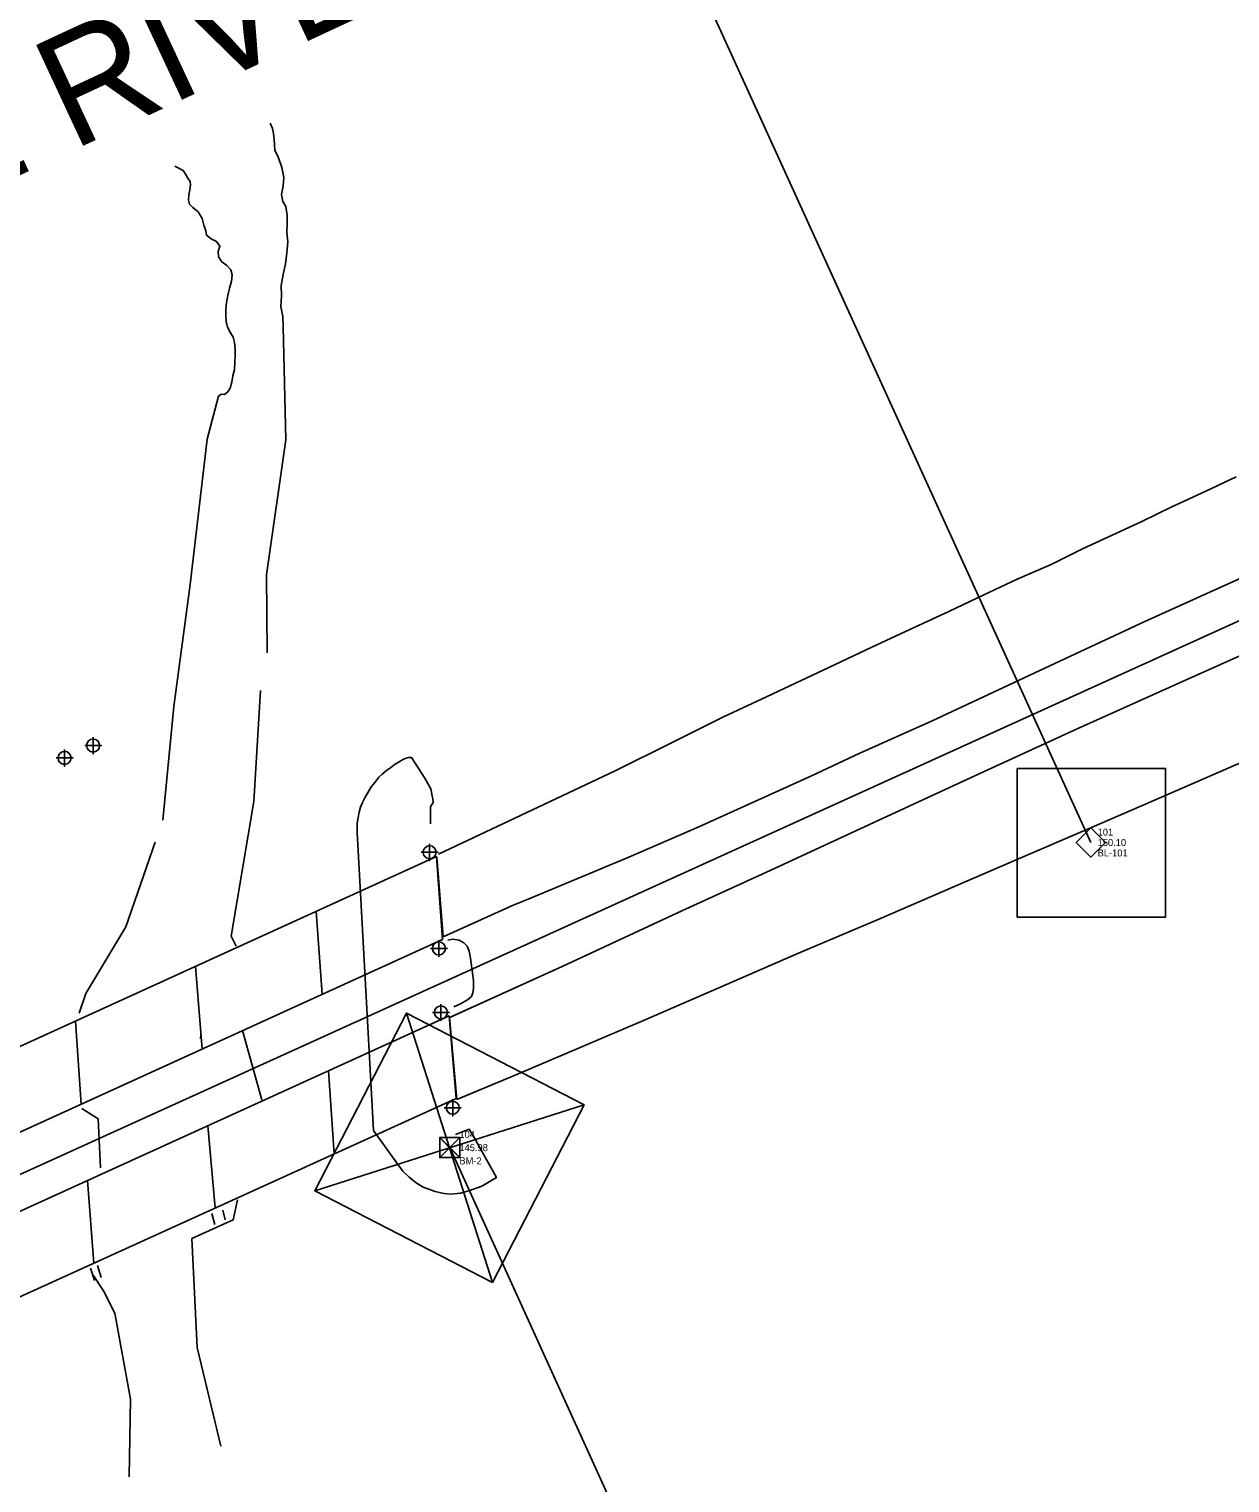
# Model space of a CAD drawing. Extents: x 2243531 to 2252747, y 658714 to 667210.
# Drawn here: x 2248974 to 2249406, y 663262 to 663785 of the extents above; entities that cross this region are included whole.
import ezdxf

# ---------------------------------------------------------------- set-up
doc = ezdxf.new("R2010")
doc.units = 0
for name, color, linetype in [('CTL Bench Mark CELL', 7, 'Continuous'), ('CTL Bench Mark Cogo Comment', 7, 'Continuous'), ('CTL Bench Mark Cogo Elevation', 7, 'Continuous'), ('CTL Bench Mark Cogo Number', 7, 'Continuous'), ('CTL NGS Horizontal CELL', 7, 'Continuous'), ('CTL Supplemental Horizontal and Vertical CELL', 7, 'Continuous'), ('CTL Supplemental Horizontal and Vertical Cogo Comment', 7, 'Continuous'), ('CTL Supplemental Horizontal and Vertical Cogo Elevation', 7, 'Continuous'), ('CTL Supplemental Horizontal and Vertical Cogo Number', 7, 'Continuous'), ('Exist Building', 7, 'Continuous'), ('Exist DTM Regular Point CELL', 7, 'Continuous'), ('Exist Hydro Stream or Body of Water', 7, 'Continuous'), ('Exist Hydro Stream or Body of Water Text', 7, 'Continuous'), ('Exist Other Culture Area Outline', 7, 'Continuous'), ('Exist Roads EOP', 7, 'Continuous'), ('Exist Structure Major Bridge Seam', 7, 'Continuous'), ('Exist Structure Major Deck Tunnel Box Culvert', 7, 'Continuous'), ('Exist Utilities Sanitary Sewer AG Line Cogo Point CELL', 7, 'Continuous'), ('Prop Horizontal Alignment', 7, 'Continuous')]:
    doc.layers.add(name, color=color, linetype=linetype)

# ---------------------------------------------------------------- blocks, each defined once
blk = doc.blocks.new('CTL BENCH MARK')
at = {"layer": 'CTL Bench Mark CELL'}
blk.add_line((0, 0), (0, 0), dxfattribs=at)
blk.add_lwpolyline([(-0.072, 0.07175), (0.07175, 0.07175), (0.07175, -0.072), (-0.072, -0.072)], close=True, dxfattribs=at)
for points in [[(0.07175, 0.07175), (-0.072, -0.072), (-0.000125, -0.000125), (0.07175, -0.072), (-0.072, 0.07175)], [(-0.000125, -0.000125), (0.07175, 0.07175), (-0.072, 0.07175), (-0.000125, -0.000125)], [(-0.000125, -0.000125), (-0.072, -0.072), (0.07175, -0.072), (-0.000125, -0.000125)]]:
    blk.add_lwpolyline(points, dxfattribs=at)

msp = doc.modelspace()

# ---------------------------------------------------------------- linework, layer by layer
at = {"layer": 'CTL Bench Mark CELL'}
msp.add_line((2249125.57, 663382.51), (2249125.57, 663382.51), dxfattribs=at)
msp.add_line((2249125.57, 663382.51), (2249125.57, 663382.51), dxfattribs=at)
for points in [[(2249110.03, 663430.9), (2249173.9, 663397.94), (2249140.94, 663334.07), (2249077.07, 663367.03)], [(2249121.97, 663386.1), (2249129.16, 663386.1), (2249129.16, 663378.91), (2249121.97, 663378.91)]]:
    msp.add_lwpolyline(points, close=True, dxfattribs=at)
for points in [[(2249173.9, 663397.94), (2249077.07, 663367.03), (2249125.48, 663382.48), (2249140.94, 663334.07), (2249110.03, 663430.9)], [(2249125.48, 663382.48), (2249173.9, 663397.94), (2249110.03, 663430.9), (2249125.48, 663382.48)], [(2249125.48, 663382.48), (2249077.07, 663367.03), (2249140.94, 663334.07), (2249125.48, 663382.48)], [(2249129.16, 663386.1), (2249121.97, 663378.91), (2249125.56, 663382.5), (2249129.16, 663378.91), (2249121.97, 663386.1)], [(2249125.56, 663382.5), (2249129.16, 663386.1), (2249121.97, 663386.1), (2249125.56, 663382.5)], [(2249125.56, 663382.5), (2249121.97, 663378.91), (2249129.16, 663378.91), (2249125.56, 663382.5)]]:
    msp.add_lwpolyline(points, dxfattribs=at)
at = {"layer": 'CTL NGS Horizontal CELL'}
for p, q in [((2249355.99, 663492.2), (2249171.33, 663897.43)), ((2249125.57, 663382.51), (2249398.31, 662783.98))]:
    msp.add_line(p, q, dxfattribs=at)
at = {"layer": 'CTL Supplemental Horizontal and Vertical CELL'}
msp.add_line((2249355.99, 663492.2), (2249355.99, 663492.2), dxfattribs=at)
msp.add_line((2249355.99, 663492.2), (2249355.99, 663492.2), dxfattribs=at)
for points in [[(2249329.53, 663518.84), (2249382.9, 663518.84), (2249382.9, 663465.38), (2249329.53, 663465.38)], [(2249350.78, 663492.22), (2249356.02, 663497.46), (2249361.27, 663492.21), (2249356.03, 663486.97)]]:
    msp.add_lwpolyline(points, close=True, dxfattribs=at)
at = {"layer": 'Exist Building'}
msp.add_lwpolyline([(2249124.85, 663457.1), (2249126.66, 663457.44), (2249129.03, 663457.08), (2249130.68, 663456.17), (2249131.84, 663454.99), (2249132.58, 663453.19), (2249133.08, 663450.58), (2249134.12, 663442.59), (2249134.16, 663439.75), (2249133.89, 663438.18), (2249133.42, 663436.82), (2249132, 663435.63), (2249129.47, 663434.25), (2249127.04, 663433.17)], dxfattribs=at)
at = {"layer": 'Exist DTM Regular Point CELL'}
for points in [[(2249118.36, 663491.68), (2249118.36, 663485.68), (2249118.36, 663488.68), (2249121.36, 663488.68), (2249115.36, 663488.68)], [(2249121.67, 663457.14), (2249121.67, 663451.14), (2249121.67, 663454.14), (2249124.67, 663454.14), (2249118.67, 663454.14)], [(2249122.42, 663434.14), (2249122.42, 663428.14), (2249122.42, 663431.14), (2249125.42, 663431.14), (2249119.42, 663431.14)], [(2249126.64, 663399.88), (2249126.64, 663393.88), (2249126.64, 663396.88), (2249129.64, 663396.88), (2249123.64, 663396.88)]]:
    msp.add_lwpolyline(points, dxfattribs=at)
for centre in [(2249118.36, 663488.68), (2249121.67, 663454.14), (2249122.42, 663431.14), (2249126.64, 663396.88)]:
    msp.add_circle(centre, 2.34, dxfattribs=at)
at = {"layer": 'Exist Hydro Stream or Body of Water'}
for p, q in [((2249065.73, 663677.55), (2249066.64, 663636.91)), ((2249038.37, 663637.24), (2249042.46, 663652.6))]:
    msp.add_line(p, q, dxfattribs=at)
for points in [[(2249061.02, 663750.86), (2249061.84, 663748.84), (2249062.29, 663747.05), (2249062.49, 663744.92)], [(2249065.73, 663677.55), (2249065.64, 663681.31), (2249064.93, 663684.9), (2249065.16, 663688.71), (2249065.03, 663692.42), (2249065.69, 663696.4), (2249066.49, 663700.18), (2249067.06, 663704.14), (2249067.42, 663708.16), (2249067.05, 663711.65), (2249067.11, 663714.73), (2249067.14, 663717.74), (2249066.64, 663720.83), (2249065.57, 663722.6), (2249065.11, 663725.16), (2249065.75, 663728.26), (2249065.96, 663731.21), (2249065.2, 663734.92), (2249064.03, 663738.34), (2249062.68, 663741.06), (2249062.49, 663744.92)], [(2249026.78, 663735.33), (2249029.78, 663733.77), (2249030.82, 663732.14), (2249031.5, 663731.04)], [(2249031.5, 663731.04), (2249031.5, 663731.04), (2249032.23, 663729.85), (2249032.43, 663728.66), (2249032.1, 663726.82), (2249031.76, 663725.01), (2249031.66, 663723.11), (2249032.09, 663721.71), (2249033.22, 663720.54), (2249035.12, 663718.9), (2249036.57, 663716.57), (2249037.21, 663714.17), (2249037.97, 663712.08), (2249038.2, 663710.51), (2249039.88, 663709.19), (2249041.74, 663708.27), (2249042.96, 663706.58), (2249042.36, 663704.61), (2249042.46, 663702.77), (2249043.62, 663700.93), (2249045.4, 663699.68), (2249046.86, 663698.13), (2249047.39, 663696.28), (2249047.18, 663694), (2249046.42, 663691.54), (2249045.82, 663688.89), (2249045.31, 663686.31), (2249045.14, 663684.1), (2249045.15, 663681.76), (2249045.23, 663679.49), (2249045.67, 663677.46), (2249046.75, 663675.48), (2249047.75, 663673.86), (2249048.24, 663671.99), (2249048.43, 663669.68), (2249048.49, 663667.26), (2249048.37, 663664.91), (2249048.2, 663662.22), (2249047.66, 663660.01), (2249047.2, 663657.75), (2249046.7, 663655.52), (2249045.67, 663654.09), (2249044.59, 663653.29), (2249043.41, 663653.4), (2249042.46, 663652.6)], [(2249022.44, 663500.21), (2249026.42, 663541.08), (2249032.24, 663584.97), (2249038.37, 663637.24)], [(2249066.64, 663636.91), (2249059.66, 663588.47), (2249059.92, 663560.38)], [(2249048.87, 663454.89), (2249047.04, 663458.48), (2249055.21, 663506.91), (2249057.52, 663546.8)], [(2248992.36, 663430.87), (2248994.77, 663437.93), (2249009.16, 663461.86), (2249019.73, 663492.37)], [(2249058.09, 663399.69), (2249051.04, 663424.61)], [(2249000.08, 663375.26), (2248999.2, 663392.91), (2248993.35, 663396.62)], [(2249043.28, 663275.16), (2249034.74, 663310.69), (2249032.88, 663349.79), (2249047.74, 663356.61), (2249049.28, 663363.69)], [(2249010.31, 663264.12), (2249010.83, 663292.06), (2249005.15, 663322.96), (2249001.16, 663330.99), (2248997.43, 663336.68)]]:
    msp.add_lwpolyline(points, dxfattribs=at)
at = {"layer": 'Exist Other Culture Area Outline'}
msp.add_line((2249106.69, 663376.77), (2249098.21, 663388.67), dxfattribs=at)
for points in [[(2249098.21, 663388.67), (2249092.27, 663495.75), (2249092.34, 663499.12), (2249092.65, 663501.16), (2249092.99, 663503.09), (2249093.5, 663504.95), (2249094.23, 663506.57), (2249095.1, 663508.23), (2249096.4, 663510.56), (2249097.39, 663512.19), (2249098.2, 663513.21), (2249099.14, 663514.43), (2249100.13, 663515.68), (2249101.26, 663516.79), (2249102.88, 663518.09), (2249104.39, 663519.21), (2249105.94, 663520.32), (2249107.43, 663521.23), (2249108.96, 663522.13), (2249110.67, 663522.75), (2249111.88, 663522.74), (2249116.58, 663515.39), (2249118.82, 663511.54), (2249119.5, 663507.77), (2249119.58, 663506.58), (2249118.68, 663505.01), (2249118.65, 663498.96)], [(2249134.33, 663386.18), (2249132.58, 663389.1), (2249127.68, 663387.18)], [(2249134.33, 663386.18), (2249142.35, 663371.73), (2249137.15, 663368.68), (2249132.42, 663366.98), (2249129.41, 663366.12), (2249125.94, 663365.8), (2249123.51, 663365.97), (2249120.33, 663366.74), (2249115.99, 663368.34), (2249113.54, 663369.81), (2249111, 663371.88), (2249108.76, 663374.1), (2249106.69, 663376.77), (2249105.76, 663378.29)], [(2249040.12, 663358.88), (2249041.11, 663354.93)], [(2249044.07, 663360.03), (2249044.89, 663356.58)], [(2248996.48, 663339.15), (2248997.89, 663334.73)], [(2248999.01, 663340.09), (2249000.33, 663335.86)]]:
    msp.add_lwpolyline(points, dxfattribs=at)
at = {"layer": 'Exist Roads EOP'}
msp.add_line((2249185.02, 663517.98), (2249121.56, 663487.99), dxfattribs=at)
for points in [[(2249748.92, 663712.77), (2249733.4, 663705.13), (2249725.89, 663702.15), (2249693.85, 663687.77), (2249660.73, 663672.87), (2249633.88, 663661.38), (2249603.61, 663647.21), (2249563.33, 663629.32), (2249529.77, 663614.02), (2249493.93, 663597.97), (2249458.47, 663581.35), (2249425.6, 663566.47), (2249386.57, 663548.98), (2249351.1, 663533.06), (2249316.09, 663516.96), (2249277.98, 663499.39), (2249240.81, 663482.13), (2249208.98, 663467.59), (2249166.03, 663447.67), (2249125.56, 663429.26)], [(2249748.92, 663712.77), (2249733.4, 663705.13), (2249725.89, 663702.15), (2249693.85, 663687.77), (2249660.73, 663672.87), (2249633.88, 663661.38), (2249603.61, 663647.21), (2249563.33, 663629.32), (2249529.77, 663614.02), (2249493.93, 663597.97), (2249458.47, 663581.35), (2249425.6, 663566.47), (2249386.57, 663548.98), (2249351.1, 663533.06), (2249316.09, 663516.96), (2249277.98, 663499.39), (2249240.81, 663482.13), (2249208.98, 663467.59), (2249166.03, 663447.67), (2249125.89, 663429.41)], [(2249128.12, 663399.86), (2249149.1, 663408.54), (2249173.29, 663418.91), (2249195.22, 663428.26), (2249222.36, 663439.97), (2249251, 663452.41), (2249280.38, 663464.92), (2249306.39, 663476.13), (2249330.07, 663486.34), (2249354.62, 663496.92), (2249378.7, 663507.27), (2249425.8, 663527.78), (2249474.22, 663549.62), (2249516.79, 663569.63), (2249561.98, 663591), (2249598.11, 663607.75), (2249632.26, 663623.87), (2249670.79, 663642.03), (2249705.32, 663658.14), (2249742.5, 663675.66), (2249776.59, 663691.66)], [(2249128.35, 663399.96), (2249149.1, 663408.54), (2249173.29, 663418.91), (2249195.22, 663428.26), (2249222.36, 663439.97), (2249251, 663452.41), (2249280.38, 663464.92), (2249306.39, 663476.13), (2249330.07, 663486.34), (2249354.62, 663496.92), (2249378.7, 663507.27), (2249425.8, 663527.78), (2249474.22, 663549.62), (2249516.79, 663569.63), (2249561.98, 663591), (2249598.11, 663607.75), (2249632.26, 663623.87), (2249670.79, 663642.03), (2249705.32, 663658.14), (2249742.5, 663675.66), (2249776.59, 663691.66)], [(2249542.9, 663647.1), (2249509.73, 663631.88), (2249471.24, 663614.74), (2249436.95, 663599.03), (2249410.14, 663587.36), (2249375.48, 663571.69), (2249346.95, 663558.33), (2249298.73, 663535.83), (2249272.97, 663524.36), (2249255.33, 663516.02), (2249215.08, 663497.83), (2249189.93, 663486.88), (2249155.17, 663472.43), (2249148.14, 663469.51), (2249123.21, 663458.27)], [(2249542.41, 663646.88), (2249509.73, 663631.88), (2249471.24, 663614.74), (2249436.95, 663599.03), (2249410.14, 663587.36), (2249375.48, 663571.69), (2249346.95, 663558.33), (2249298.73, 663535.83), (2249272.97, 663524.36), (2249255.33, 663516.02), (2249215.08, 663497.83), (2249189.93, 663486.88), (2249155.17, 663472.43), (2249148.14, 663469.51), (2249123.21, 663458.27)], [(2249408.32, 663623.66), (2249397.37, 663618.54), (2249385.15, 663612.87), (2249374.34, 663607.65), (2249353.09, 663597.78), (2249341.72, 663592.12), (2249329.59, 663586.84), (2249315.32, 663580.13), (2249304.97, 663575.3), (2249290.99, 663568.77), (2249277.26, 663562.37), (2249266.14, 663557.13), (2249241.44, 663545.58), (2249223.79, 663537.31), (2249205.29, 663528.07), (2249185.02, 663517.98)], [(2249408.32, 663623.66), (2249397.37, 663618.54), (2249385.15, 663612.87), (2249374.34, 663607.65), (2249353.09, 663597.78), (2249341.72, 663592.12), (2249329.59, 663586.84), (2249315.32, 663580.13), (2249304.97, 663575.3), (2249290.99, 663568.77), (2249277.26, 663562.37), (2249266.14, 663557.13), (2249241.44, 663545.58), (2249223.79, 663537.31), (2249205.29, 663528.07), (2249185.02, 663517.98)], [(2249123.21, 663458.27), (2249120.96, 663486.92)], [(2249119.96, 663426.71), (2249119.93, 663426.7)], [(2249128.12, 663399.86), (2249125.56, 663429.26)]]:
    msp.add_lwpolyline(points, dxfattribs=at)
at = {"layer": 'Exist Structure Major Bridge Seam'}
for p, q in [((2249079.78, 663437.67), (2249077.55, 663467.42)), ((2249036.54, 663417.97), (2249034.14, 663447.64)), ((2248993.09, 663398.17), (2248991.06, 663428.01)), ((2249036.01, 663421.62), (2249036.11, 663423.33)), ((2249083.99, 663380.24), (2249082.03, 663410.13)), ((2249041.3, 663360.83), (2249038.62, 663390.37)), ((2248997.65, 663340.99), (2248995.43, 663370.7))]:
    msp.add_line(p, q, dxfattribs=at)
at = {"layer": 'Exist Structure Major Deck Tunnel Box Culvert'}
for points in [[(2248906.6, 663358.76), (2248904.48, 663388.56), (2249120.82, 663487.13), (2249123, 663457.36), (2248906.6, 663358.76)], [(2248911.14, 663301.65), (2248908.74, 663331.22), (2249125.33, 663429.85), (2249127.92, 663400.22), (2248911.14, 663301.65)]]:
    msp.add_lwpolyline(points, dxfattribs=at)
at = {"layer": 'Exist Utilities Sanitary Sewer AG Line Cogo Point CELL'}
for points in [[(2248997.38, 663530.06), (2248997.38, 663524.06), (2248997.38, 663527.06), (2249000.38, 663527.06), (2248994.38, 663527.06)], [(2248987.14, 663525.59), (2248987.14, 663519.59), (2248987.14, 663522.59), (2248990.14, 663522.59), (2248984.14, 663522.59)]]:
    msp.add_lwpolyline(points, dxfattribs=at)
for centre in [(2248997.38, 663527.06), (2248987.14, 663522.59)]:
    msp.add_circle(centre, 2.34, dxfattribs=at)
at = {"layer": 'Prop Horizontal Alignment'}
msp.add_line((2247500.8, 662705.02), (2249793.08, 663746.29), dxfattribs=at)

# ---------------------------------------------------------------- block references
at = {"layer": 'CTL Bench Mark CELL', "xscale": 50, "yscale": 50}
msp.add_blockref('CTL BENCH MARK', (2249125.57, 663382.51), dxfattribs=at)

# ---------------------------------------------------------------- texts
at = {"layer": 'CTL Bench Mark Cogo Comment'}
msp.add_text('BM-2', height=2.5, dxfattribs=at).set_placement((2249129.07, 663376.51))
at = {"layer": 'CTL Bench Mark Cogo Elevation'}
msp.add_text('145.98', height=2.5, dxfattribs=at).set_placement((2249129.07, 663381.26))
at = {"layer": 'CTL Bench Mark Cogo Number'}
msp.add_text('104', height=2.5, dxfattribs=at).set_placement((2249129.07, 663386.01))
at = {"layer": 'CTL Supplemental Horizontal and Vertical Cogo Comment'}
msp.add_text('BL-101', height=2.5, dxfattribs=at).set_placement((2249358.49, 663487.2))
msp.add_text('BL-101', height=2.5, dxfattribs=at).set_placement((2249358.49, 663487.2))
at = {"layer": 'CTL Supplemental Horizontal and Vertical Cogo Elevation'}
msp.add_text('150.10', height=2.5, dxfattribs=at).set_placement((2249358.49, 663490.95))
msp.add_text('150.10', height=2.5, dxfattribs=at).set_placement((2249358.49, 663490.95))
at = {"layer": 'CTL Supplemental Horizontal and Vertical Cogo Number'}
msp.add_text('101', height=2.5, dxfattribs=at).set_placement((2249358.49, 663494.7))
msp.add_text('101', height=2.5, dxfattribs=at).set_placement((2249358.49, 663494.7))
at = {"layer": 'Exist Hydro Stream or Body of Water Text'}
msp.add_text('LITTLE RIVER', height=39.9995, rotation=24.9875, dxfattribs=at).set_placement((2248817.41, 663660.43))

doc.saveas('drawing.dxf')
